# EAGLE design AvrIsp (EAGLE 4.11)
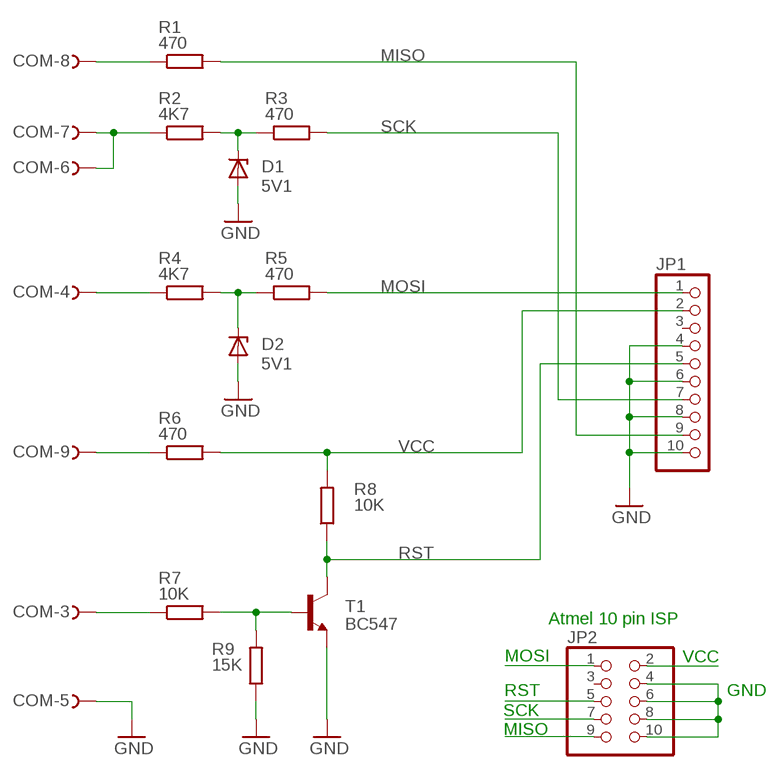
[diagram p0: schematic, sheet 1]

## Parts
COM  F09HPS  [F09HP]
D1  5V1  ZENER-DIODEDO34-7  [DO34Z7]
D2  5V1  ZENER-DIODEDO34-7  [DO34Z7]
JP1  PINHD-1X10  [1X10]
JP2  PINHD-2X5  [2X05]
R1  470  R-EU_0204/7  [0204/7]
R2  4K7  R-EU_0204/7  [0204/7]
R3  470  R-EU_0207/10  [0207/10]
R4  4K7  R-EU_0204/7  [0204/7]
R5  470  R-EU_0207/10  [0207/10]
R6  470  R-EU_0204/7  [0204/7]
R7  10K  R-EU_0204/7  [0204/7]
R8  10K  R-EU_0207/10  [0207/10]
R9  15K  R-EU_0204/7  [0204/7]
T1  BC547  [TO92]

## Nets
GND: COM.5 D1.A D2.A JP1.4 JP1.6 JP1.8 JP1.10 R9.1 T1.1(E)
MISO: JP1.9 R1.2
MOSI: JP1.1 R5.2
N$1: D1.C R2.2 R3.1
N$2: D2.C R4.2 R5.1
N$3: COM.8 R1.1
N$4: COM.6 COM.7 R2.1
N$5: COM.4 R4.1
N$8: R7.2 R9.2 T1.2(B)
N$9: COM.9 R6.1
N$10: COM.3 R7.1
N$83: JP2.1
N$84: JP2.5
N$85: JP2.7
N$86: JP2.9
N$87: JP2.2
N$88: JP2.4 JP2.6 JP2.8 JP2.10
RST: JP1.5 R8.1 T1.3(C)
SCK: JP1.7 R3.2
VCC: JP1.2 R6.2 R8.2
Unconnected: COM.1 COM.2 JP1.3 JP2.3

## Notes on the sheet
- Atmel 10 pin ISP
- MOSI | VCC
- RST | GND
- SCK
- MISO

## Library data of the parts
COM = con-subd:F09?S: SUB-D
D1 D2 = diode:ZENER-DIODE: Z-Diode
JP1 = pinhead:PINHD-1X10: PIN HEADER
JP2 = pinhead:PINHD-2X5: PIN HEADER
R1-R9 = rcl:R-EU_: RESISTOR, European symbol
T1 = transistor:BC547: NPN TRANSISTOR

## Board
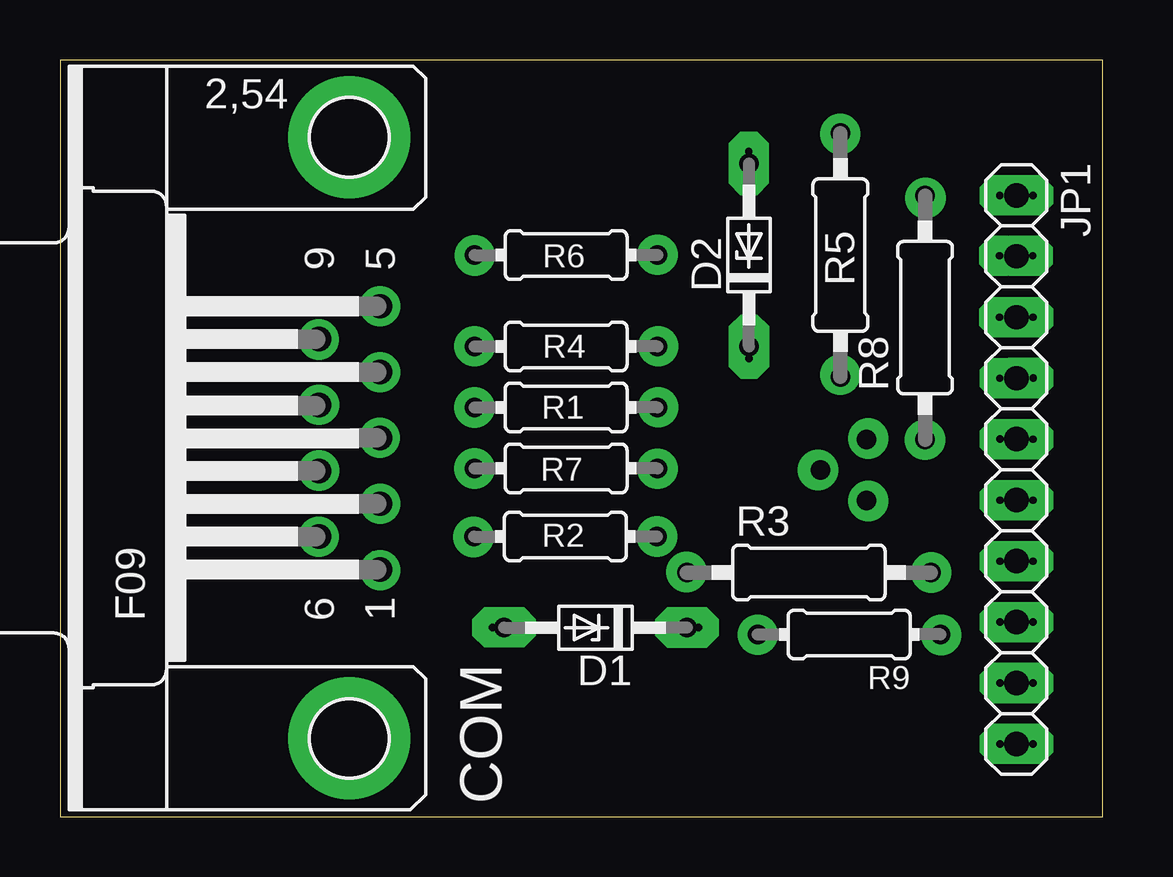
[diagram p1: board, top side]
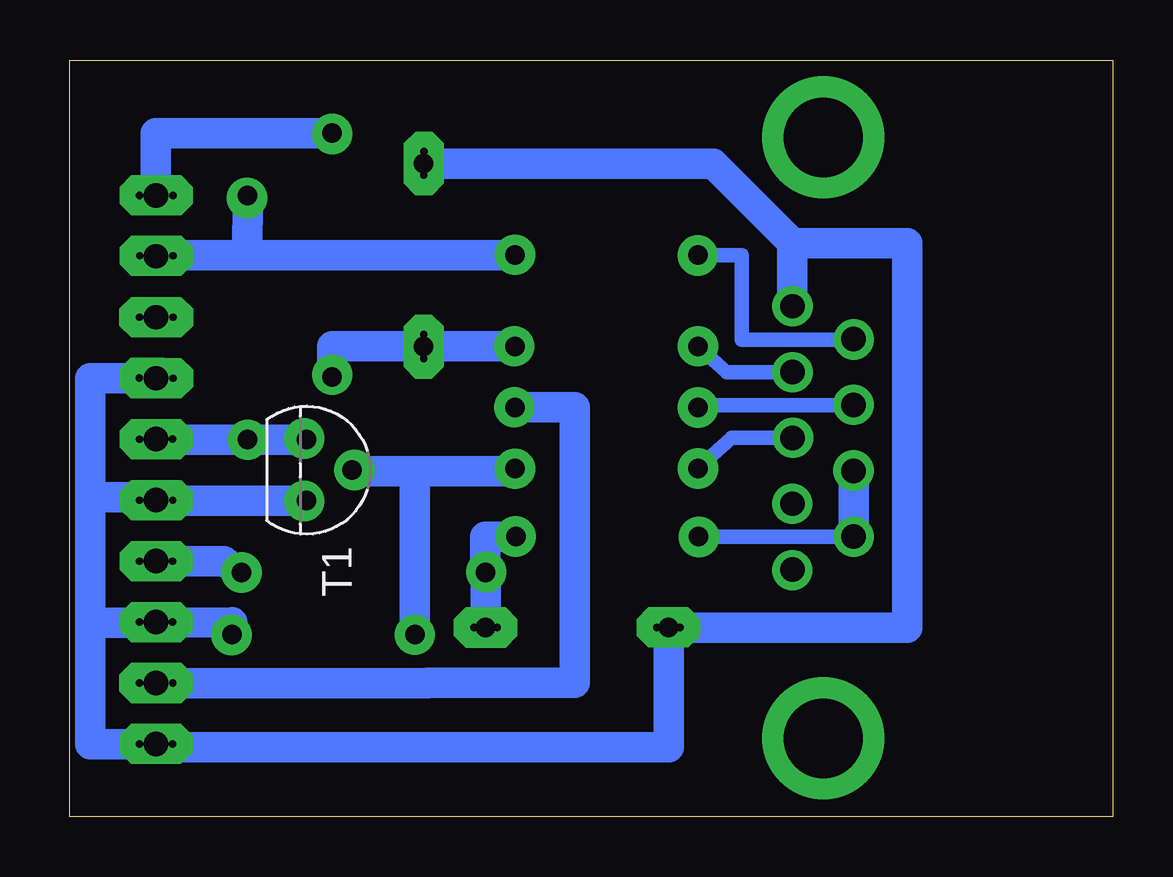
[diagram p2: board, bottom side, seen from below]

Size 43.44 x 31.53 mm. Coordinates in mm from the lower left corner, seen from the top.
Outline: 0,0 43.44,0 43.44,31.53 0,31.53 0,0
Copper layers (1*16): Top 0.035mm / dielectric 1.5mm / Bottom 0.035mm
Design rules "default": minimum track width 10mil, minimum drill 24mil, track to track 8mil, track to pad 8mil, pad to pad 8mil, via to via 8mil, smd to smd 8mil, copper to edge 40mil, drill to drill 8mil, minimum pad ring 10mil, minimum via ring 8mil, stop-mask expansion 4mil, vias tented up to drill 0mil, thermal gap 10mil

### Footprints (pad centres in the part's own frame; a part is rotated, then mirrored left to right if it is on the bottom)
F09HP = drill 1.016 octagon: 1 -5.486,-1.27; 2 -2.743,-1.27; 3 0,-1.27; 4 2.743,-1.27; 5 5.486,-1.27; 6 -4.115,1.27; 7 -1.372,1.27; 8 1.372,1.27; 9 4.115,1.27 | drill 3.302 pad 5.08 round: G1 -12.522,0; G2 12.522,0
DO34Z7 = drill 0.813 long: A 3.81,0; C -3.81,0
1X10 = drill 1.016 long: 1 -11.43,0; 2 -8.89,0; 3 -6.35,0; 4 -3.81,0; 5 -1.27,0; 6 1.27,0; 7 3.81,0; 8 6.35,0; 9 8.89,0; 10 11.43,0
2X05 = drill 1.016 octagon: 1 -5.08,-1.27; 2 -5.08,1.27; 3 -2.54,-1.27; 4 -2.54,1.27; 5 0,-1.27; 6 0,1.27; 7 2.54,-1.27; 8 2.54,1.27; 9 5.08,-1.27; 10 5.08,1.27
0204/7 = drill 0.813 octagon: 1 -3.81,0; 2 3.81,0
0207/10 = drill 0.813 octagon: 1 -5.08,0; 2 5.08,0
TO92 = drill 0.813 octagon: 1 1.27,0; 2 0,1.905; 3 -1.27,0

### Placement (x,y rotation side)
COM  12.06,15.78 90 top
D1  22.31,7.88 180 top
D2  28.71,23.4 90 top
JP1  39.85,14.46 270 top
JP2  not placed on the board
R1  21.09,17.05 0 top
R2  21.06,11.68 0 top
R3  31.2,10.18 0 top
R4  21.09,19.59 0 top
R5  32.52,23.4 90 top
R6  21.09,23.4 0 top
R7  21.09,14.51 0 top
R8  36.04,20.8 90 top
R9  32.88,7.59 180 top
T1  33.59,14.44 270 bottom

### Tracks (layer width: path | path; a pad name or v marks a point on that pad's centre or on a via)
GND
  Bottom 0.406: 39.66,13.22 39.66,13.19 JP1.6 | 39.66,13.32 39.66,13.22 | 39.66,13.22 39.88,13.22 39.88,13.17 | 39.88,8.11 39.88,8.12 | 39.88,8.11 JP1.8 | 36.69,7.63 R9.1 | 39.88,8.09 39.88,8.11 | JP1.10 39.85,2.9 39.82,2.9
  Bottom 1.27: 39.88,13.17 T1.1 | 36.69,7.63 36.69,8.11 39.88,8.09 42.54,8.09 42.54,8.15 42.59,8.15 | JP1.4 42.59,18.27 42.59,13.37 | 42.59,8.15 42.59,3.03 39.82,3.03 | 42.59,8.15 42.59,13.37 | 42.59,13.37 42.54,13.37 42.54,13.32 39.66,13.32 | 39.82,3.03 39.82,2.9 18.5,2.9 D1.A 8.55,7.88 8.55,23.89 13.34,23.89 | 39.82,3.03 39.82,3.12 | D2.A 16.65,27.21 13.34,23.91 13.34,23.89 | 13.34,23.89 13.34,23.83 13.34,21.27 COM.5
MISO
  Bottom 0.406: 39.74,5.57 39.74,5.61 | 39.74,5.57 JP1.9 | 39.74,5.57
  Bottom 1.27: R1.2 22.42,17.05 22.42,5.58 28.54,5.58 28.54,5.57 39.74,5.57
MOSI
  Bottom 0.406: 39.87,25.87 39.87,25.89 JP1.1
  Bottom 1.27: R5.2 39.87,28.48 39.87,25.89
N$1
  Bottom 0.406: 26.14,9.79 26.14,9.87 R3.1 26.12,9.88 | 26.12,7.77 D1.C
  Bottom 1.27: R2.2 26.14,11.67 26.14,9.87 | 26.12,9.88 D1.C
N$2
  Bottom 1.27: R4.2 D2.C 32.52,19.59 R5.1
N$3
  Bottom 0.61: R1.1 17.23,17.05 17.23,17.15 COM.8
N$4
  Bottom 0.61: COM.6 16.17,11.67 R2.1
  Bottom 1.27: COM.6 COM.7
N$5
  Bottom 0.61: COM.4 16.07,18.53 R4.1
N$6  (via drill 0.3 pad 1.68)
  other vias: 17.28,23.39
N$7  (via drill 0.3 pad 1.68)
  other vias: 17.27,19.6
N$8
  Bottom 0.406: 31.77,14.4 31.69,14.4 T1.2 | 24.98,14.4 R7.2 | 29.06,14.4 29.06,14.38 29.07,14.38
  Bottom 1.27: 24.98,14.4 29.06,14.4 31.69,14.4 | R9.2 29.07,14.38
N$9
  Bottom 0.406: COM.9 10.91,19.9 10.91,19.88 10.91,19.84
  Bottom 0.61: R6.1 15.46,23.4 15.46,19.88 10.91,19.88
N$10
  Bottom 0.61: COM.3 15.87,15.78 R7.1
N$11  (via drill 0.3 pad 1.68)
  other vias: 17.27,17.05
N$12  (via drill 0.3 pad 1.68)
  other vias: 17.27,14.51
N$13  (via drill 0.3 pad 1.68)
  other vias: 17.23,11.66
N$14  (via drill 0.3 pad 1.68)
  other vias: 24.9,23.42
N$15  (via drill 0.3 pad 1.68)
  other vias: 24.93,19.6
N$16  (via drill 0.3 pad 1.68)
  other vias: 24.93,17.06
N$17  (via drill 0.3 pad 1.68)
  other vias: 24.9,14.5
N$18  (via drill 0.3 pad 1.68)
  other vias: 24.88,11.68
N$19  (via drill 0.3 pad 1.68)
  other vias: 26.1,10.2
N$20  (via drill 0.3 pad 1.68)
  other vias: 29.08,7.59
N$21  (via drill 0.3 pad 1.68)
  other vias: 36.71,7.57
N$22  (via drill 0.3 pad 1.68)
  other vias: 36.3,10.18
N$23  (via drill 0.3 pad 1.68)
  other vias: 33.68,13.15
N$24  (via drill 0.3 pad 1.68)
  other vias: 31.59,14.45
N$25  (via drill 0.3 pad 1.68)
  other vias: 33.68,15.75
N$26  (via drill 0.3 pad 1.68)
  other vias: 36.04,15.7
N$27  (via drill 0.3 pad 1.68)
  other vias: 32.51,18.41
N$28  (via drill 0.3 pad 1.68)
  other vias: 32.51,28.44
N$29  (via drill 0.3 pad 1.68)
  other vias: 36.07,25.78
N$30  (via drill 0.3 pad 1.68)
  other vias: 13.34,10.27
N$31  (via drill 0.3 pad 1.68)
  other vias: 13.34,13.04
N$32  (via drill 0.3 pad 1.68)
  other vias: 10.79,11.67
N$33  (via drill 0.3 pad 1.68)
  other vias: 10.79,14.43
N$34  (via drill 0.3 pad 1.68)
  other vias: 13.32,15.79
N$35  (via drill 0.3 pad 1.68)
  other vias: 10.79,17.16
N$36  (via drill 0.3 pad 1.68)
  other vias: 13.33,18.52
N$37  (via drill 0.3 pad 1.68)
  other vias: 10.79,19.89
N$38  (via drill 0.3 pad 1.68)
  other vias: 13.34,21.27
N$39  (via drill 0.3 pad 1.68)
  other vias: 25.64,7.88
N$40  (via drill 0.3 pad 1.68)
  other vias: 26.6,7.88
N$41  (via drill 0.3 pad 1.68)
  other vias: 26.15,7.88
N$42  (via drill 0.3 pad 1.68)
  other vias: 18.99,7.89
N$43  (via drill 0.3 pad 1.68)
  other vias: 18.02,7.89
N$44  (via drill 0.3 pad 1.68)
  other vias: 18.48,7.89
N$45  (via drill 0.3 pad 1.68)
  other vias: 28.7,27.71
N$46  (via drill 0.3 pad 1.68)
  other vias: 28.7,26.74
N$47  (via drill 0.3 pad 1.68)
  other vias: 28.7,27.3
N$48  (via drill 0.3 pad 1.68)
  other vias: 28.7,19.09
N$49  (via drill 0.3 pad 1.68)
  other vias: 28.7,20.09
N$50  (via drill 0.3 pad 1.68)
  other vias: 28.7,19.6
N$51  (via drill 0.3 pad 1.68)
  other vias: 39.15,25.89
N$52  (via drill 0.3 pad 1.68)
  other vias: 40.54,25.89
N$53  (via drill 0.3 pad 1.68)
  other vias: 39.84,25.89
N$54  (via drill 0.3 pad 1.68)
  other vias: 39.15,23.37
N$55  (via drill 0.3 pad 1.68)
  other vias: 40.53,23.37
N$56  (via drill 0.3 pad 1.68)
  other vias: 39.87,23.37
N$57  (via drill 0.3 pad 1.68)
  other vias: 39.15,20.81
N$58  (via drill 0.3 pad 1.68)
  other vias: 40.55,20.81
N$59  (via drill 0.3 pad 1.68)
  other vias: 39.85,20.81
N$60  (via drill 0.3 pad 1.68)
  other vias: 39.15,18.27
N$61  (via drill 0.3 pad 1.68)
  other vias: 40.55,18.28
N$62  (via drill 0.3 pad 1.68)
  other vias: 39.85,18.28
N$63  (via drill 0.3 pad 1.68)
  other vias: 39.16,15.73
N$64  (via drill 0.3 pad 1.68)
  other vias: 40.54,15.73
N$65  (via drill 0.3 pad 1.68)
  other vias: 39.85,15.73
N$66  (via drill 0.3 pad 1.68)
  other vias: 39.16,13.19
N$67  (via drill 0.3 pad 1.68)
  other vias: 40.54,13.19
N$68  (via drill 0.3 pad 1.68)
  other vias: 39.85,13.19
N$69  (via drill 0.3 pad 1.68)
  other vias: 39.16,10.65
N$70  (via drill 0.3 pad 1.68)
  other vias: 40.54,10.65
N$71  (via drill 0.3 pad 1.68)
  other vias: 39.85,10.65
N$72  (via drill 0.3 pad 1.68)
  other vias: 39.16,8.11
N$73  (via drill 0.3 pad 1.68)
  other vias: 40.54,8.11
N$74  (via drill 0.3 pad 1.68)
  other vias: 39.86,8.11
N$75  (via drill 0.3 pad 1.68)
  other vias: 39.16,5.57
N$76  (via drill 0.3 pad 1.68)
  other vias: 40.54,5.57
N$77  (via drill 0.3 pad 1.68)
  other vias: 39.85,5.57
N$78  (via drill 0.3 pad 1.68)
  other vias: 39.17,3.04
N$79  (via drill 0.3 pad 1.68)
  other vias: 40.54,3.04
N$80  (via drill 0.3 pad 1.68)
  other vias: 39.85,3.04
N$81  (via drill 0.3 pad 3.81)
  other vias: 12.02,28.25
N$82  (via drill 0.3 pad 3.81)
  other vias: 12.05,3.23
N$88  (3 unrouted)
RST
  Bottom 0.406: R8.1 36.06,15.68 | 39.92,15.73 39.92,15.74 | 39.92,15.73 JP1.5 | 39.92,15.72 39.92,15.73
  Bottom 1.27: T1.3 R8.1 | R8.1 39.92,15.72
SCK
  Bottom 0.406: 39.92,10.64 JP1.7
  Bottom 1.27: R3.2 37.03,10.64 JP1.7
VCC
  Bottom 0.406: JP1.2 39.86,23.4 | 36.08,23.4 36.05,23.45
  Bottom 1.27: R6.2 36.08,23.4 39.86,23.4 | 36.05,23.45 R8.2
